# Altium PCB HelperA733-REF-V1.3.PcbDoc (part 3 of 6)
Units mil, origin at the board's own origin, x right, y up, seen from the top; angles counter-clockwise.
Board outline 5905.51 x 4133.86 mil, 2 copper layers (Top, Bottom), stack 12.7 mil thick; 446 components, 341 nets, 1706 pads, 1667 vias.
Unrouted connection lines stored in the file: 1382.
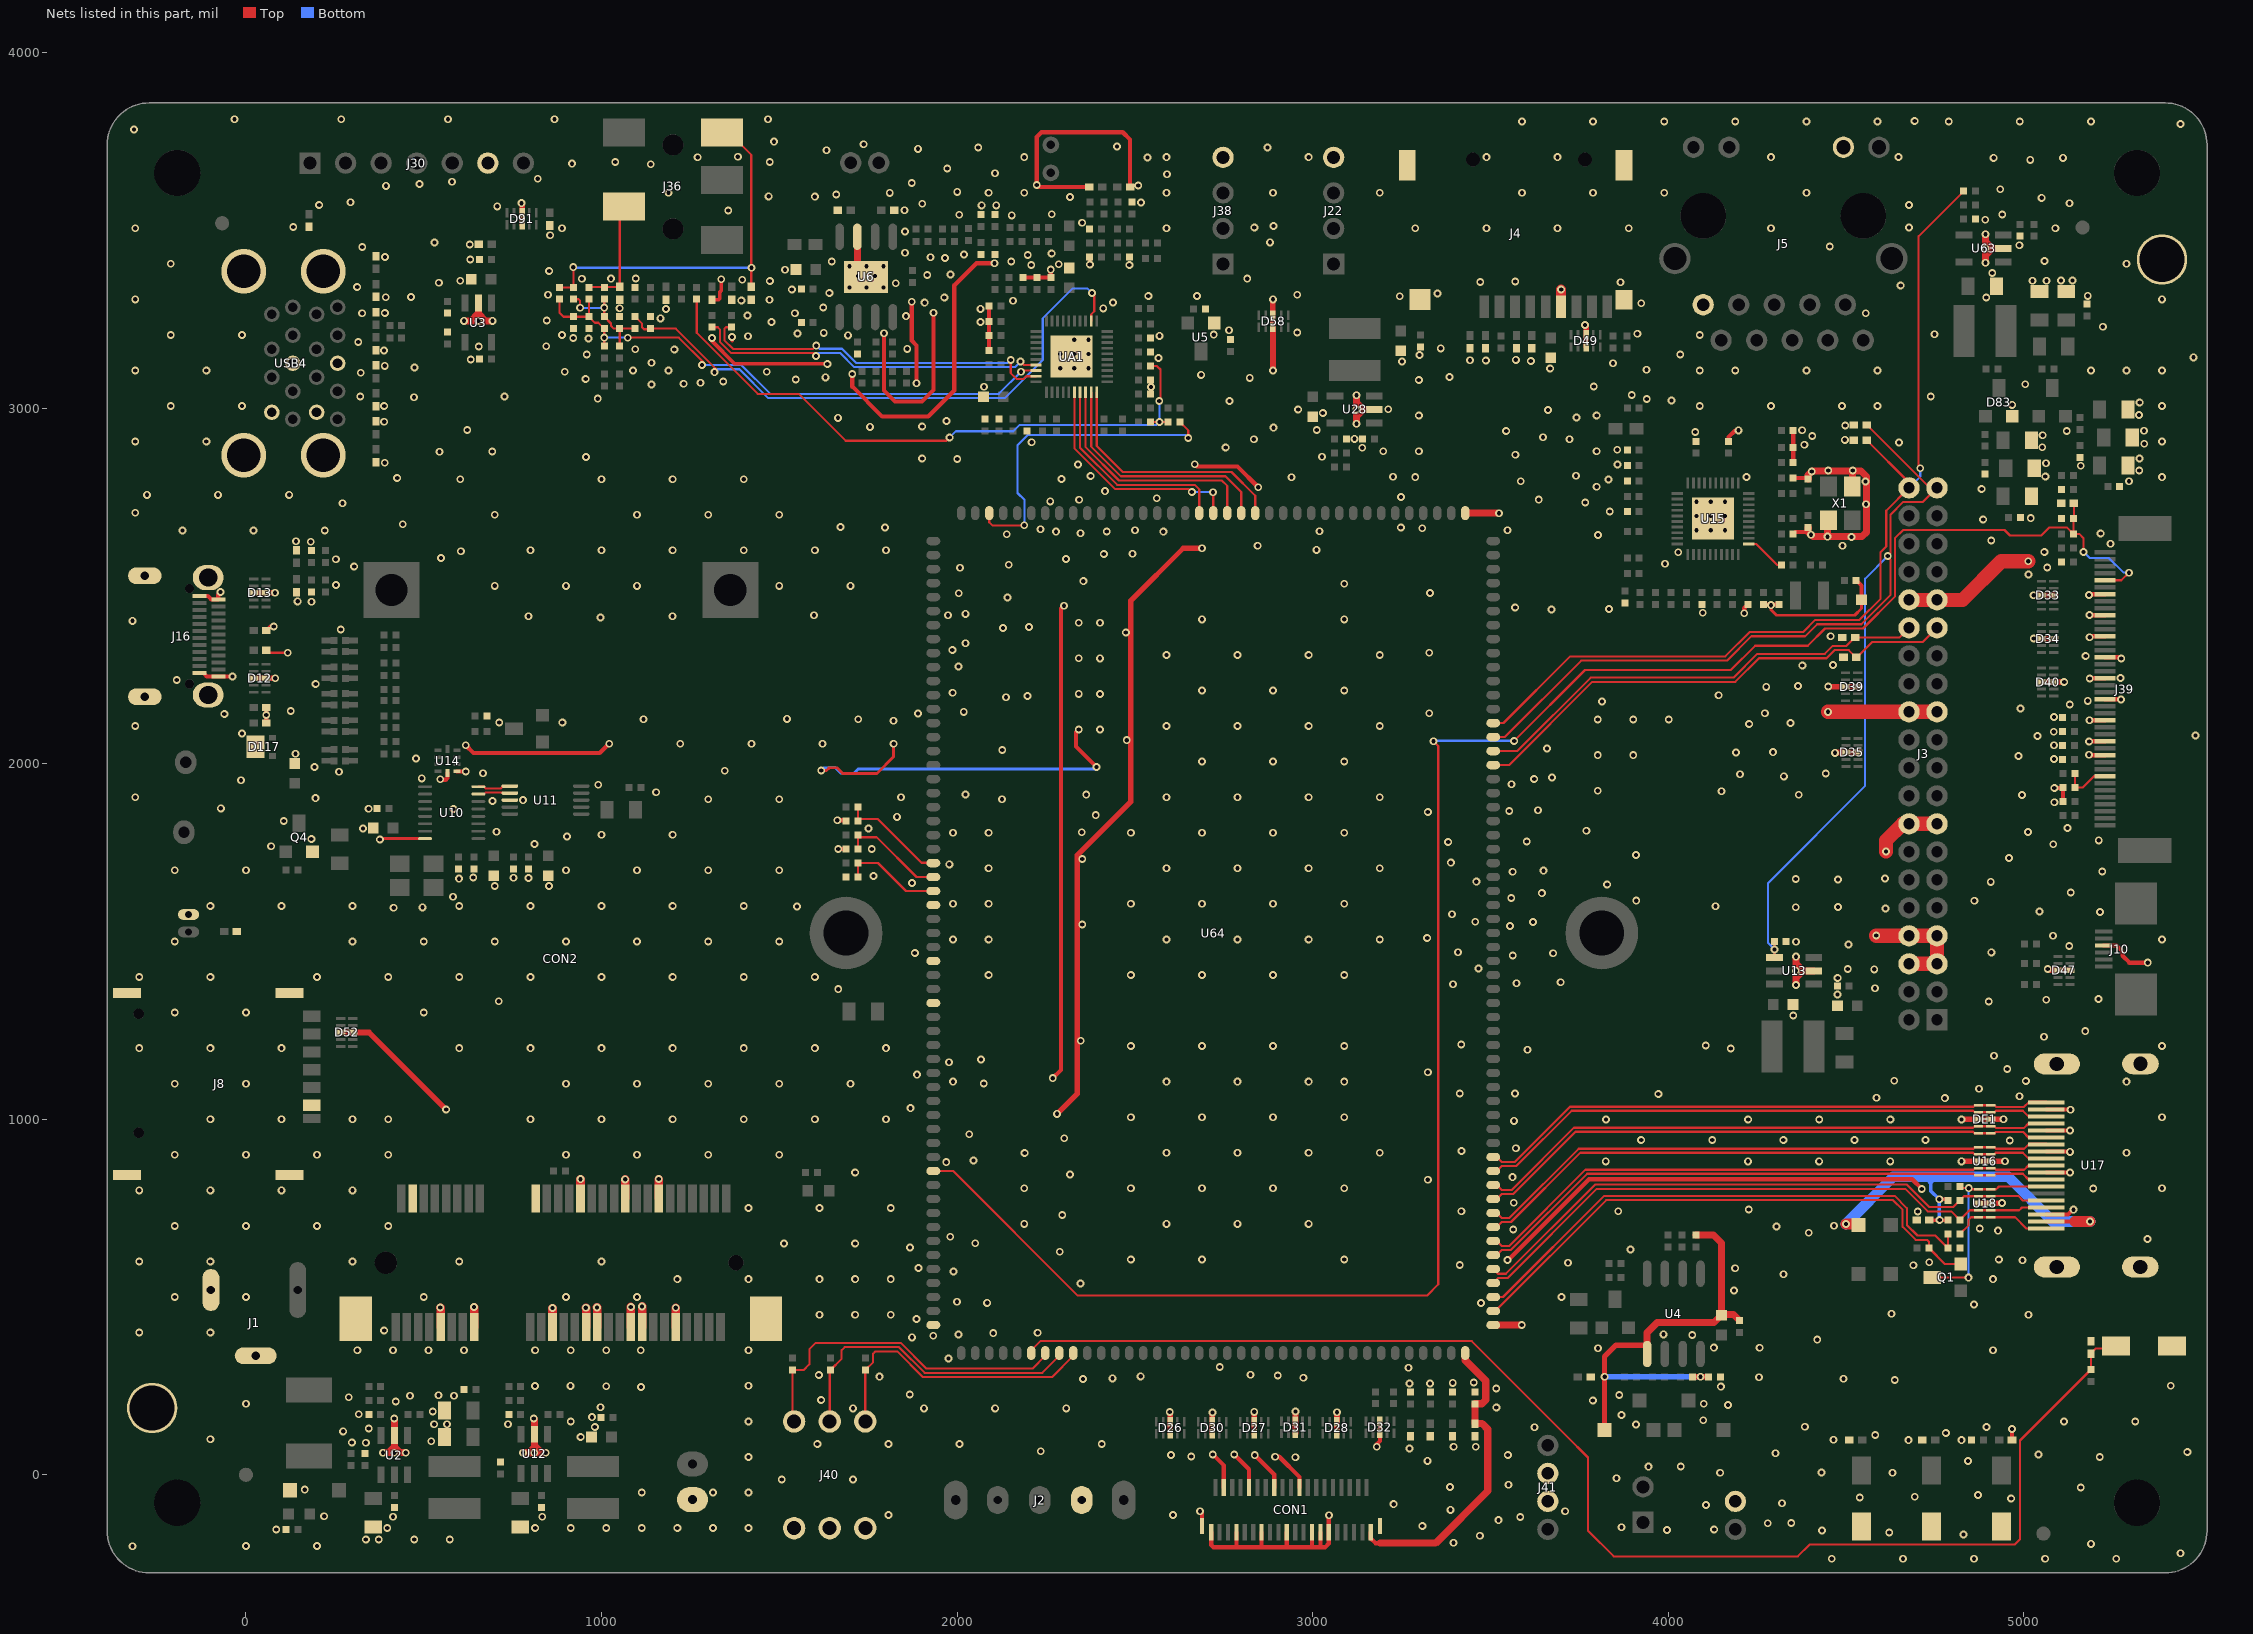
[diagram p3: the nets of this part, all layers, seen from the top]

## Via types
v1: diameter 22, hole 12, Top to Bottom, 1667 vias

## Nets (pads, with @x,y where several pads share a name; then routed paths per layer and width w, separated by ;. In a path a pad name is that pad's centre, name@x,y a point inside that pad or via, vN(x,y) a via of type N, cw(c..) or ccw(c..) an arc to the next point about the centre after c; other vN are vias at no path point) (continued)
GND: C2.2 C3.2 C4.1 C5.2 C6.2 C54.2 C55.2 C58.2 C59.2 C60.2 C69.2 C70.2 C71.2 C73.2 C75.2 C81.1 C90.2 C91.2 C94.2 C95.2 C96.2 C97.2 C173.2 C174.2 C175.2 C176.2 C177.2 C178.2 C179.2 C180.2 C183.2 C184.2 C190.2 C193.2 C197.2 C215.2 C216.2 C220.2 C223.1 C224.1 C226.1 C230.2 C231.1 C232.2 C233.2 C234.2 C235.1 CA1.1 CA2.2 CA3.1 CA4.1 CA5.1 CA10.2 CA11.2 CA12.2 CA13.2 CA14.2 CA17.2 CA18.1 CA23.2 CA25.2 CA83.1 CA89.2 CE4.1 CE5.1 CE7.1 CE8.1 CE9.1 CE11.1 CE12.1 CE13.1 CE14.1 CE15.1 CE17.1 CE18.1 CE19.1 CE20.1 CE21.1 CON1.1 CON1.4 CON1.7 CON1.10 CON1.13 CON1.16 CON1.19 CON1.22 CON1.25 CON1.27 CON1.29 CON1.40 CON1.41 CON2.4 CON2.9 CON2.15 CON2.18 CON2.21 CON2.26 CON2.27 CON2.29 CON2.34 CON2.35 CON2.37 CON2.40 CON2.43 CON2.M1 CON2.M2 CP5.2 CP6.2 CP7.2 CP8.2 CU1.1 CU2.1 CU3.1 CU7.2 D1.2 D2.1 D4.1 D5.1 D6.2 D7.2 D8.2 D9.2 D10.2 D11.2 D12.3 D12.8 D13.3 D13.8 D15.1 D16.1 D17.1 D18.1 D19.1 D20.1 D26.3 D26.8 D27.3 D27.8 D28.3 D28.8 D30.3 D30.8 D31.3 D31.8 D32.3 D32.8 D33.3 D33.8 D34.3 D34.8 D35.3 D35.8 D39.3 D39.8 D40.3 D40.8 D41.2 D42.2 D43.2 D44.2 D45.2 D47.3 D47.8 D49.3 D49.8 D52.3 D52.8 D58.3 D58.8 D67.1 D70.2 D71.2 D72.2 D73.2 D74.2 D75.2 D82.1 D83.2 D84.2 D87.2 D88.2 D90.2 D91.3 D91.8 D117.3 D118.1 D126.1 D127.1 D128.1 D129.1 D130.2 D170.2 D171.2 D172.1 D174.1 D175.1 D176.1 D177.1 D178.1 DA1.1 DA2.1 DE1.3 DE1.8 FID4.1 FID6.1 J1.2 J1.3 J2.3 J3.5 J3.6 J3.7 J3.8 J3.15 J3.16 J3.23 J3.24 J3.31 J3.32 J4.6 J4.10 J4.11 J4.12 J4.13 J5.10 J5.12 J8.5 J8.8 J8.9 J8.10 J8.11 J10.3 J14.1 J16.1 J16.2 J16.3 J16.4 J16.A1 J16.A12 J16.B1 J16.B12 J22.4 J30.6 J38.4 J39.7 J39.10 J39.13 J39.16 J39.19 J39.22 J39.25 J39.28 J39.30 J40.4 J40.5 J40.6 J41.2 J41.3 J42.2 K1.2 K2.1 K3.1 K4.2 Q4.2 R4.1 R5.2 R6.2 R25.2 R26.2 R32.2 R37.1 R38.1 R49.2 R60.1 R62.1 R150.1 R159.2 R165.1 R166.1 R174.2 R179.1 R203.2 R204.2 R205.2 R208.2 R215.2 R216.2 R217.2 R218.2 R235.2 R266.2 R279.2 R281.2 R289.2 R292.2 RA6.1 RA8.2 RA13.2 RA26.2 RA61.2 RA65.1 RE22.1 RE23.1 RE34.1 RU1.1 RU7.1 RU25.2 RU110.2 U2.2 U3.2 U5.1 U6.7 U6.9 U10.8 U11.3 U12.2 U13.2 U14.5 U14.6 U15.41 U16.3 U16.8 U17.2 U17.5 U17.8 U17.11 U17.17 U17.20 U17.21 U17.22 U17.23 U18.3 U18.8 U28.2 U63.2 U64.38 U64.95 U64.158 U64.162 U64.165 U64.188 UA1.41 USB4.4 USB4.7 USB4.13 USB4.16 USB4.19 USB4.20 USB4.21 USB4.22 X1.2 X1.4 | length 18443.2
  Top w7: D7.2@57.37,2318.9 64.78,2311.49 117.81,2311.49 v1(117.81,2311.89)
  Top w8: v1(376.65,1787.03) 378.79,1789.17 U10.8@503.94,1789.17 ; v1(1618.22,1980.71) 1618.22,1980.99 1633.23,1980.99 1640.59,1988.35 1662.26,1988.35 1678.32,1972.29 1774.41,1972.29 1821.53,2019.41 v1(1821.53,2056.01) ; v1(4288.79,2445.82) 4288.79,2432.83 4304.34,2417.28 4524.55,2417.28 4543.7,2436.43 CE7.1@4543.7,2460.63
  Top w10: v1(1310.6,3197.18) 1310.6,3188.49 1375,3124.09 v1(1635.19,3124.09) ; D17.1@1311.02,3304.83 1329.51,3304.83 1333.14,3308.46 1333.14,3326.47 1336.84,3330.17 1336.84,3362.19 v1(1336.61,3362.42) ; 1367.1,3189.01 v1(1367.1,3200.01)
  Top w11.81: J16.B1@-130.9,2254.92 -119.82,2254.92 -109.98,2245.08 J16.A12@-77.76,2245.08 -77.59,2245.25 v1(-37.99,2245.25) ; J16.B12@-130.9,2471.46 -107.17,2471.46 -97.32,2461.61 J16.A1@-77.76,2461.61 -77.76,2476.48 v1(-71.29,2482.94) ; v1(57.34,2136.92) D10.2@57.37,2157.48 ; D11.2@57.37,2114.17 v1(57.34,2136.92) ; D6.2@57.37,2374.02 69.01,2385.65 v1(78.25,2385.65) ; v1(546.26,1955.93) 547.42,1954.76 561.8,1954.76 566.93,1959.89 U14.5@566.93,1974.02 ; U14.6@593.51,1978.34 618.15,1978.34 v1(618.15,1978.17) ; v1(618.16,2051.76) 640.27,2029.65 995.17,2029.65 v1(1021.53,2056.01) ; v1(1663.31,1841.02) 1685.55,1841.02 R235.2@1687.99,1838.58 ; v1(1665.7,1759.84) R279.2@1687.99,1759.84 ; v1(1705.41,3095.77) 1705.41,3060.24 1789.33,2976.31 1919.04,2976.31 1992.03,3049.31 1992.03,3345.17 2054.25,3407.38 v1(2105.19,3407.38) ; v1(1794.74,3210.53) 1794.74,3049.27 1825.74,3018.27 1901.06,3018.27 1933.55,3050.76 v1(1933.55,3267.89) ; v1(1872.37,3298.93) 1872.37,3189.9 1885.95,3176.32 v1(1885.95,3069.84) ; CA10.2@2089.57,3161.42 CA2.2@2089.57,3204.72 RA6.1@2089.57,3244.09 CA4.1@2089.57,3287.4 ; CA14.2@2185.04,3367.13 RA8.2@2224.41,3367.13 RA26.2@2263.65,3367.13 ; v1(2263.65,3389.37) RA26.2@2263.65,3367.13 ; RA26.2@2263.78,3367.13 RA26.2@2263.65,3367.13 ; v1(2269.1,1115.59) 2292.35,1138.84 2292.35,2436.54 2299.91,2444.1 v1(2300.84,2444.1) ; v1(2342.28,2096.31) 2334.6,2088.64 2334.6,2047.96 v1(2391.98,1990.58) ; DA1.1@2371.76,3622.05 2229.44,3622.05 v1(2224.12,3627.37) 2224.12,3762.61 2237.2,3775.69 2465.95,3775.69 2486.5,3755.14 DA2.1@2486.5,3622.05 ; CA5.1@2373.03,3425.2 2373.46,3424.77 v1(2373.46,3403.8) ; v1(2668.47,2841.93) 2674.89,2835.51 2788.86,2835.51 v1(2846.9,2777.47) ; v1(2683.18,-102.26) 2689.1,-108.18 CON1.41@2689.1,-144.16 ; CON1.1@2714.69,-161.38 2714.69,-197.63 2721.06,-204 2785.56,-204 ; v1(2719.22,56.88) 2750.12,25.97 CON1.4@2750.12,-35.4 ; v1(2779.58,57.14) 2820.99,15.72 CON1.10@2820.99,-35.4 ; CON1.7@2785.56,-161.38 2785.56,-204 ; v1(2837.29,55.33) 2891.86,0.75 CON1.16@2891.86,-35.4 ; CON1.13@2856.42,-161.38 2856.42,-204 ; v1(2894.48,50.68) 2906.17,50.68 2962.72,-5.87 CON1.22@2962.72,-35.4 ; CON1.19@2927.29,-161.38 2927.29,-204 ; CON1.25@2998.15,-161.38 2998.15,-204 ; CON1.27@3021.78,-161.38 3021.78,-204 ; v1(3046.1,-113.53) 3045.4,-113.53 CON1.29@3045.4,-161.38 3045.4,-193.52 3034.92,-204 3021.78,-204 ; v1(3180.47,78.96) 3180.47,86.2 3188.98,94.71 D32.8@3188.98,116.82 D32.3@3188.98,150.9 ; v1(3548.1,603.87) 3550.04,603.87 3777.23,831.06 4686.27,831.06 4713.42,803.91 v1(4712.99,803.47) ; CE5.1@4169.29,2906.5 4169.29,2918.25 4188.39,2937.35 v1(4197.46,2937.35) ; v1(4213.58,2422.97) 4213.58,2437 RE23.1@4224.41,2447.84 ; CE14.1@4267.72,2447.84 CE12.1@4311.02,2447.84 ; R150.1@4351.38,2645.67 4357.48,2651.77 4393.46,2651.77 ; CE20.1@4351.38,2803.15 4393.64,2803.15 4393.7,2803.15 CE17.1@4393.7,2800.2 ; RE22.1@4351.38,2846.46 CE9.1@4351.38,2889.76 C81.1@4351.38,2937.01 ; CE8.1@4528.54,2515.75 4543.7,2500.59 CE7.1@4543.7,2460.63 ; D4.1@4966.82,98.43 v1(4966.82,129.01) ; U17.17@5062.99,732.28 5124.66,732.28 5138.77,746.39 v1(5139.47,745.7) ; U17.11@5062.99,850.39 5129.91,850.39 v1(5130.02,850.29) ; U17.8@5062.99,909.45 5128.68,909.45 v1(5129.93,908.2) ; U17.5@5062.99,968.5 5129.79,968.5 v1(5129.87,968.58) ; U17.2@5062.99,1027.56 5130.48,1027.56 v1(5131.21,1026.83) ; v1(5085.86,1931.56) R203.2@5110.24,1931.56 ; R204.2@5110.24,1893.7 R203.2@5110.24,1931.56 ; R203.2@5110.24,1933.07 R203.2@5110.24,1931.56 ; v1(5183.04,2025.23) 5188.31,2023.62 J39.30@5228.35,2023.62 ; v1(5183.55,2474.55) 5188.64,2476.38 J39.7@5228.35,2476.38 ; v1(5183.77,2062.18) 5188.97,2062.99 J39.28@5228.35,2062.99 ; v1(5184.42,2121.88) 5184.42,2122.05 J39.25@5228.35,2122.05 ; v1(5185.05,2418.19) 5187.41,2417.32 J39.10@5228.35,2417.32 ; v1(5185.13,2355.5) 5189.53,2358.27 J39.13@5228.35,2358.27 ; v1(5185.23,2239.29) 5190.05,2240.16 J39.19@5228.35,2240.16 ; J10.3@5224.41,1488.19 5260.85,1488.19 5277.41,1471.63 5277.41,1459.75 5296.8,1440.36 v1(5348.48,1440.36) ; J39.22@5228.35,2181.1 5270.9,2181.1 v1(5273.51,2180.27) ; J39.16@5228.35,2299.21 5269.01,2299.21 v1(5273.91,2296.03) ; 2785.56,-204 2856.42,-204 ; 2856.42,-204 2927.29,-204 ; 2927.29,-204 2998.15,-204 ; 2998.15,-204 3021.78,-204
  Top w15: D91.3@777.38,3514.99 D91.8@777.38,3549.44 ; v1(2281.16,1015.07) 2337.61,1071.52 2337.61,1742.07 2488.68,1893.14 2488.68,2458.31 2636.14,2605.77 v1(2688.7,2605.77)
  Top w16: D12.3@22.33,2240.16 D12.8@56.41,2240.16 56.48,2240.23 v1(82.49,2240.23) ; D13.3@22.33,2480.32 81.67,2480.32 v1(81.67,2480.61) ; D52.8@266.42,1244.09 D52.3@300.5,1244.09 346.46,1244.09 v1(562.99,1027.56) ; v1(774.79,3576.31) 777.38,3576.31 D91.8@777.38,3549.44 ; v1(2598.06,176.62) 2599.43,175.24 D26.8@2599.43,149.36 D26.3@2599.43,115.28 ; D30.3@2717.54,115.28 D30.8@2717.54,149.36 2717.54,174.95 v1(2718.08,175.48) ; D27.3@2835.65,115.28 2835.65,147.15 2835.74,147.23 v1(2835.74,177) ; v1(2888.7,3105.77) 2888.7,3225.87 D58.8@2887.79,3226.77 D58.3@2887.79,3261.22 2887.79,3304.87 v1(2888.7,3305.77) ; D31.3@2951.48,116.17 2951.48,148.11 2951.78,148.41 v1(2951.78,178.25) ; D28.3@3067.94,115.28 3067.94,146.55 3068.28,146.89 v1(3068.28,176.07) ; v1(3766.08,3233.43) 3769.69,3233.43 D49.8@3769.69,3206.3 D49.3@3769.69,3171.85 ; v1(4450.22,2217.01) 4450.7,2216.54 D39.8@4498.71,2216.54 D39.3@4532.79,2216.54 ; v1(4468.72,2030.41) 4469.8,2031.5 D35.8@4499.69,2031.5 D35.3@4533.77,2031.5 ; v1(4824.44,881.54) 4824.79,881.89 U16.3@4872.72,881.89 U16.8@4906.8,881.89 v1(4946.8,881.89) ; v1(4824.73,999.09) 4825.64,1000 DE1.3@4872.72,1000 DE1.8@4906.8,1000 v1(4942.72,1000) ; U18.3@4872.72,763.78 4938,763.78 v1(4938.58,764.36) ; v1(5027.59,2473.64) v1(5027.59,2473.64) D33.3@5049.89,2473.73 D33.8@5083.97,2473.73 ; v1(5028.02,2351.74) D34.3@5049.89,2351.69 D34.8@5083.97,2351.69 ; D40.3@5049.89,2229.64 D40.8@5083.97,2229.64 v1@5113.39,2229.64 ; v1(5067.2,1422.4) 5071.03,1418.57 D47.3@5095.93,1418.57 D47.8@5130.01,1418.57
  Top w20: v1(385.32,62.24) 405.32,62.24 ; v1(417.32,158.24) U2.2@417.32,110.24 417.32,78.24 ; v1(449.32,62.24) 433.32,62.24 ; v1(613.54,3245.28) 633.54,3245.28 ; U3.2@653.54,3295.28 653.54,3265.28 ; v1(693.54,3245.28) 673.54,3245.28 ; v1(779.02,62.17) 795.02,62.17 ; v1@811.02,156.54 U12.2@811.02,114.17 811.02,78.17 ; v1(843.02,62.17) 831.02,62.17 ; U6.7@1719.4,3481.79 1719.4,3397.73 1721.2,3395.93 v1(1721.2,3371.17) ; v1(3123.23,2956.06) 3123.23,2976.06 ; v1(3123.23,3036.06) 3123.23,3016.06 ; U28.2@3173.23,2996.06 3143.23,2996.06 ; U64.95@3429.13,2704.73 3516.58,2704.72 v1(3524,2704) ; U64.38@3507.87,421.26 v1(3587.87,421.26) ; v1(4359.45,1377.32) 4359.45,1397.32 ; v1(4359.45,1457.32) 4359.45,1437.32 ; CE18.1@4393.7,2664.37 4393.46,2651.77 4406.65,2638.58 v1@4447.88,2638.58 ; CE17.1@4393.7,2800.2 4393.64,2803.15 4393.46,2811.96 4403.27,2821.77 4404.59,2823.09 v1@4517.72,2823.09 ; U13.2@4409.45,1417.32 4379.45,1417.32 ; v1(4447.88,2638.43) v1@4447.88,2638.58 ; X1.2@4450.79,2685.04 4447.88,2682.13 v1@4447.88,2638.58 ; X1.4@4517.72,2779.53 v1@4517.72,2823.09 ; v1(4891.93,3408.82) 4891.93,3428.82 ; v1(4891.93,3488.82) 4891.93,3468.82 ; U63.2@4941.93,3448.82 4911.93,3448.82 ; 405.32,62.24 405.32,66.24 417.32,78.24 ; 405.32,62.24 v1(417.32,62.24) ; v1(417.32,62.24) 433.32,62.24 ; v1(417.32,62.24) 417.32,78.24 ; 417.32,78.24 433.32,62.24 ; 633.54,3245.28 653.54,3265.28 ; 633.54,3245.28 v1(653.54,3245.28) ; v1(653.54,3245.28) 673.54,3245.28 ; v1(653.54,3245.28) 653.54,3265.28 ; 653.54,3265.28 673.54,3245.28 ; 795.02,62.17 v1(811.02,62.17) ; 795.02,62.17 807.02,74.17 811.02,74.17 ; v1(811.02,62.17) 831.02,62.17 ; v1(811.02,62.17) 811.02,74.17 ; 811.02,74.17 811.02,78.17 ; 811.02,78.17 815.02,78.17 831.02,62.17 ; 3123.23,2976.06 3143.23,2996.06 ; 3123.23,2976.06 v1(3123.23,2996.06) ; v1(3123.23,2996.06) 3123.23,3016.06 ; v1(3123.23,2996.06) 3143.23,2996.06 ; 3123.23,3016.06 3143.23,2996.06 ; 4359.45,1397.32 v1(4359.45,1417.32) ; 4359.45,1397.32 4379.45,1417.32 ; v1(4359.45,1417.32) 4359.45,1437.32 ; v1(4359.45,1417.32) 4379.45,1417.32 ; 4359.45,1437.32 4379.45,1417.32 ; v1@4447.88,2638.58 4545.07,2638.58 4557.34,2650.85 4557.34,2807.71 4541.96,2823.09 v1@4517.72,2823.09 ; 4891.93,3428.82 v1(4891.93,3448.82) ; 4891.93,3428.82 4911.93,3448.82 ; v1(4891.93,3448.82) 4891.93,3468.82 ; v1(4891.93,3448.82) 4911.93,3448.82 ; 4891.93,3468.82 4911.93,3448.82
  Top w24: v1(546.55,470.23) 547.25,470.23 CON2.9@547.25,415.42 ; v1(641.52,471.69) 641.74,471.47 CON2.15@641.74,415.42 ; v1(861.87,468.86) 862.21,468.86 CON2.21@862.21,415.42 ; v1(940.83,831.58) 940.95,831.58 CON2.26@940.95,777.62 ; v1(955.93,470.08) 956.7,470.08 CON2.27@956.7,415.42 ; v1(987.04,470.62) 988.19,470.62 CON2.29@988.19,415.42 ; v1(1066.45,830.87) 1066.93,830.87 CON2.34@1066.93,777.62 ; v1(1082.53,472.26) 1082.68,472.26 CON2.35@1082.68,415.42 ; CON2.37@1114.18,415.42 v1(1114.18,473.35) ; v1(1160.79,831.81) 1161.42,831.81 CON2.40@1161.42,777.62 ; v1(1208.58,470.08) 1208.66,470.08 CON2.43@1208.66,415.42
  Top w28: J4.6@3698.82,3285.43 v1(3698.82,3333.43)
  Top w40: v1(4449.38,2145.67) J3.24@4677.17,2145.67 4711.46,2145.67 J3.23@4755.91,2145.67 ; v1(4585.01,1516.71) 4585.01,1516.23 4677.17,1516.23 J3.8@4677.17,1515.75 J3.7@4755.91,1515.75 J3.5@4755.91,1437.01 J3.6@4677.17,1437.01 ; v1(4612.74,1752.97) 4612.74,1783.97 4659.48,1830.71 J3.16@4677.17,1830.71 J3.15@4755.91,1830.71 ; J3.32@4677.17,2460.63 4715.74,2460.63 J3.31@4755.91,2460.63 4827.91,2460.63 4936.33,2569.05 v1(5012.26,2569.05)
  Bottom w8: v1(1618.22,1980.71) 1618.22,1980.98 1625.59,1988.35 1658.1,1988.35 1673.58,1972.87 1710.16,1972.87 1722,1984.72 2386.11,1984.72 v1(2391.98,1990.58)
  other v1: 4460,-236 4660,-236 4860,-236 5060,-236 5260,-236 5440.94,-220.47 -318.9,-200.79 0,-200 200,-200 5188.7,-194.23 3396.22,-190.89 337.32,-181.76 373.32,-181.76 473.32,-181.76 573.32,-181.76 3470.18,-171.46 4830.08,-168.15 4621.41,-162.03 4432.51,-156.37 3996.67,-155.12 85.32,-153.76 4129.03,-153.88 397.32,-149.76 813.32,-149.76 913.32,-149.76 1013.32,-149.76 1113.32,-149.76 1213.32,-149.76 1313.32,-149.76 1413.32,-149.76 3868.86,-147.68 3308.45,-144.26 4280,-136 4345.96,-135.2 3522.94,-127.53 3584.04,-118.48 413.32,-117.76 833.32,-117.76 219.95,-116.69 1807.04,-113.16 2607.04,-113.16 3710.01,-102.64 3387.42,-98.57 4106.46,-84.83 3227.72,-82.46 4320,-80 4964.33,-66.41 4538.5,-64.05 4693.48,-61.7 4871.13,-56.71 1113.32,-49.76 1313.32,-49.76 1413.32,-49.76 165.32,-41.76 5160,-36 3386.42,-34 3550.85,-27.97 1507.04,-13.16 1707.04,-13.16 3854.59,-9.59 4630.83,5.66 4145.99,5.71 4430.91,6.49 3944.5,22.93 4035.04,23.57 4842.8,38.64 3322.75,39.18 2951.38,49.37 1413.32,50.24 5213.32,50.24 2658.39,51.42 2601.39,55.75 3548.97,55.93 5041.5,56.95 4301.6,60.83 5460,64 2235.14,66.03 3272.62,74.2 3396.53,78.92 3458.68,78.92 1607.04,86.84 1807.04,86.84 2007.04,86.84 2407.04,86.84 337.32,90.24 297.95,91.16 521.32,94.24 4675.9,97.53 4825.05,97.53 4464.73,98.52 -100,100 941.32,106.24 4582.09,111.84 4780.74,117.62 273.32,122.24 345.32,130.24 981.32,134.24 3623.84,133.85 4894.87,134.23 4384.28,134.96 529.32,142.24 565.32,142.24 737.32,142.24 3909.45,141.73 913.32,150.24 1413.32,150.24 5113.32,150.24 5313.32,150.24 4098.43,153.54 809.32,158.24 973.32,162.24 3868.7,168.21 317.32,170.24 525.32,178.24 1707.04,186.84 1907.04,186.84 2107.04,186.84 2307.04,186.84 3516.64,189.26 997.32,190.24 4167.82,196.55 0,200 4100,200 421.32,206.24 3787.99,209.13 1617.72,210.1 289.32,218.24 461.32,222.24 585.32,222.24 541.44,223.73 3862.26,224.67 1867.04,225.56 3516.3,242.89 1110.85,247 4148,248 1013.2,249.22 812.99,249.72 913.01,250.11 1413.32,250.24 5413.32,250.24 3272.08,256.66 3330.18,257.03 3393.93,258.57 3452.93,259.62 4636.89,266.72 2353.79,269.71 4493.18,270.37 2436.79,271.28 2973.83,272.99 4255.21,274.39 1781.58,276.14 2516.25,276.88 2901.74,279.47 1611.27,280.77 2824.9,281.2 3269.48,301.01 2738.51,303.33 1975.63,327 313.32,350.24 413.32,350.24 513.32,350.24 613.32,350.24 813.32,350.24 913.32,350.24 1013.32,350.24 1110.34,350.19 1413.32,350.24 4913.32,350.24 3802.79,355.99 4257,357.38 4128.28,357.71 4419.03,380.16 1873.3,386.5 1933.07,391.26 4067.5,393.02 2003.93,394.8 3986.9,395.05 2101.47,398.48 2226.49,399.39 -300,400 -100,400 388.7,405.77 1885.76,438.37 1613.32,450.24 1713.32,450.24 1813.32,450.24 5013.32,450.24 4628.14,453.02 4859.83,479.3 2084.58,483.59 3473.44,483.33 1999.51,486.53 -200,500 0,500 500,500 900,500 1100,500 3700,500 4185.19,518.22 2346.89,537.77 1213.32,550.24 1413.32,550.24 1613.32,550.24 1713.32,550.24 1813.32,550.24 4913.32,550.24 4324.4,564.03 1990.01,571.52 1891.51,581.51 4188.16,580.69 4689.37,589.35 3413.43,590.38 3718.13,596.42 4734.03,597.93 -300,600 -100,600 300,600 600,600 1000,600 4996.23,603.29 4929.81,605.33 2488.7,605.77 2688.7,605.77 3088.7,605.77 2288.77,627.13 3893.99,633.75 1867.77,639.07 1513.32,650.24 1713.32,650.24 2051.21,651.23 5347.72,662.96 1980.89,669.29 4395.31,680.61 4927.1,686.66 3564.11,689.78 4876.27,692.76 4304.67,698.52 -200,700 0,700 200,700 400,700 4466.08,700.64 2188.7,705.77 2588.7,705.77 2788.7,705.77 2988.7,705.77 2295.93,730.99 4701.96,740.26 3418.19,741.26 3859.32,740.99 4226.54,746.44 1413.32,750.24 1613.32,750.24 1813.32,750.24 3565.5,765.11 -300,800 -100,800 100,800 300,800 5195.23,805.29 2188.7,805.77 2488.7,805.77 2688.7,805.77 2888.7,805.77 3088.7,805.77 5388.7,805.77 3324,830 3562.04,837.2 2317.35,844.87 1713.32,850.24 1969.65,879.33 3824.44,881.54 4224.44,881.54 4424.44,881.54 4624.44,881.54 2045.91,883.75 -200,900 0,900 200,900 400,900 900,900 1100,900 1300,900 1500,900 2190.03,905.18 2588.7,905.77 2788.7,905.77 2988.7,905.77 3188.7,905.77 5288.7,905.77 3418.62,910.78 3571.43,918.2 4960.23,940.43 3923.77,941.37 4123.77,941.37 4323.77,941.37 4523.77,941.37 4723.77,941.37 2301.27,946.72 2034.15,957.84 3566.19,995.37 3824.73,999.09 4224.73,999.09 4424.73,999.09 4624.73,999.09 -100,1000 100,1000 300,1000 400,1000 800,1000 1000,1000 1200,1000 1400,1000 1600,1000 1800,1000 2488.7,1005.77 2688.7,1005.77 2888.7,1005.77 3088.7,1005.77 5388.7,1005.77 1868.96,1031.15 4778.02,1059.38 4585.42,1060.44 4987.64,1064.7 3972.22,1071.26 3413.55,1072.16 3569.26,1072.06 4873.79,1085.98 -200,1100 0,1100 900,1100 1100,1100 1300,1100 1500,1100 1700,1100 2075.16,1100.43 1988.7,1105.77 2588.7,1105.77 2788.7,1105.77 2988.7,1105.77 3088.7,1105.77 5288.7,1105.77 5005.73,1107.26 4635.44,1108.33 1887.41,1125.45 3324,1132 4953.58,1141.14 1977.12,1160.09 2067.01,1167.73 4916.35,1178.56 3604.08,1195.17 4175.85,1198.92 -300,1200 -100,1200 100,1200 600,1200 800,1200 1000,1200 1200,1200 1400,1200 1600,1200 1800,1200 2488.7,1205.77 2688.7,1205.77 2888.7,1205.77 3088.7,1205.77 5388.7,1205.77 4105.36,1207.05 3418,1210 2347.77,1220.52 5056.81,1231.76 5172.79,1247.72 4351.71,1291.66 -200,1300 0,1300 500,1300 4901.29,1330.95 711.02,1332.03 5063.19,1336.04 5210.03,1338.17 4476.12,1350.57 1665.71,1365.9 4581.64,1368.29 3394.71,1379.71 3573.36,1382.35 3697.39,1385.06 4476.44,1397.08 -300,1400 -100,1400 200,1400 400,1400 600,1400 800,1400 1000,1400 1200,1400 1400,1400 1600,1400 2088.7,1405.77 2488.7,1405.77 2688.7,1405.77 2888.7,1405.77 3088.7,1405.77 4579.51,1421.5 4505.03,1422.56 3466.46,1423.97 3562.77,1460.79 1881.23,1467.59 3676.3,1466.84 4908.74,1469.28 3408.45,1469.77 5127.93,1487.37 4506.67,1491.29 4359.04,1498.95 -200,1500 300,1500 500,1500 700,1500 900,1500 1100,1500 1300,1500 1500,1500 1988.7,1505.77 2088.7,1505.77 2588.7,1505.77 2788.7,1505.77 2988.7,1505.77 3188.7,1505.77 5388.7,1505.77 3322,1510 5082.18,1516.1 3555.28,1543.43 2352.24,1547.56 3619.6,1554.65 3457.3,1555.25 3391.66,1576.62 5214.12,1583.14 5043.87,1584.2 4611.17,1592.9 415.4,1594.54 496.73,1595.89 4358.37,1596.29 4477.65,1596.97 1549.99,1598.6 4132.8,1599.15 -100,1600 100,1600 300,1600 600,1600 800,1600 1000,1600 1200,1600 1400,1600 1988.7,1605.77 2088.7,1605.77 2488.7,1605.77 2688.7,1605.77 2888.7,1605.77 3088.7,1605.77 4860.86,1614.6 3910.12,1614.81 3558.3,1621.99 582.13,1625.71 3644.64,1635.81 5132.19,1637.4 699.68,1655.69 852.56,1655.8 3828.11,1660.22 1873.5,1664.14 4907.07,1667.54 3460.35,1668.21 4477.65,1674.23 4358.37,1675.58 599.5,1676.64 4609.81,1676.94 794.9,1678.54 639.5,1679.68 752.24,1678.92 1765.1,1683.85 3562.39,1695.87 5220.51,1696.99 3649.28,1699.17 -200,1700 0,1700 900,1700 1100,1700 1300,1700 1500,1700 2088.7,1705.77 2588.7,1705.77 2788.7,1705.77 2988.7,1705.77 3188.7,1705.77 1978.29,1716.75 3388.61,1721.64 2352.24,1731.7 4958.45,1734.45 3909.44,1742.91 1759.84,1759.84 70.87,1767.72 5082.89,1773.25 811.44,1774.18 3380.97,1779.64 3602.31,1781.17 5210.93,1784.24 184,1788 902.67,1795.15 1000,1800 1200,1800 1988.7,1805.77 2088.7,1805.77 2488.7,1805.77 2688.7,1805.77 2888.7,1805.77 3088.7,1805.77 2350.39,1807.09 704.5,1808.29 5011.9,1807.95 3769.74,1811.35 329.07,1817.95 1750.58,1817.97 5122.89,1819.25 106.3,1838.58 1830.71,1850.39 2390.11,1855.25 3324,1864 3552.67,1866.68 3633.54,1868.81 583.92,1872.37 345.06,1873.18 -70.47,1874.3 5085.86,1891.56 693.41,1895.17 779.19,1897.37 1300,1900 1500,1900 2126.64,1899.86 195.39,1903.04 1842.52,1905.51 -311.3,1905.77 2588.7,1905.77 2788.7,1905.77 2988.7,1905.77 3188.7,1905.77 4995.2,1911.53 2023.62,1913.39 2363.25,1912.91 4367.18,1912.8 1153.7,1919.36 4150.02,1922.39 3801.65,1923.95 990.86,1940.89 3559.06,1942.23 -14.09,1953.34 3622.9,1957.13 494.38,1958.6 3672.91,1961.38 4325.16,1964.3 4201.81,1970.4 4443.09,1972.44 666.74,1973.01 261.77,1977.38 1346.62,1980.3 193.05,1990.71 2688.7,2005.77 2888.7,2005.77 3088.7,2005.77 5085,2013.14 478.09,2014.2 4985.34,2021.6 3801.65,2023.95 3901.65,2023.95 139.37,2027.62 4190.38,2031.16 4294.41,2032.45 2126.84,2038.25 3659.18,2042.92 5084.66,2051.8 1221.53,2056.01 1421.53,2056.01 1621.53,2056.01 2477.03,2066.13 5038.2,2077.85 5482.53,2078.96 -11.06,2085.02 5084.31,2089.78 2402.17,2096.08 -311.3,2105.77 2588.7,2105.77 2788.7,2105.77 2988.7,2105.77 3188.7,2105.77 4227.57,2111.78 4344.14,2114.49 712.25,2115.74 889.95,2115.74 1820.91,2120.87 3801.65,2123.95 3901.65,2123.95 4001.65,2123.95 1118.13,2125.13 1722.1,2125.13 1521.91,2125.98 5084.66,2131.2 -60.66,2139.88 1889.89,2140.81 4271.68,2141.54 3328,2142 2018.53,2145.72 125.86,2147.78 4990.76,2155.11 5129.02,2166.63 3813.51,2175.01 5179.85,2176.61 2137.64,2186.52 2197.84,2190.12 4141.72,2192.53 2342.28,2196.31 2402.17,2196.08 1987.54,2199.35 2688.7,2205.77 2888.7,2205.77 3088.7,2205.77 4275.84,2216.03 4365.15,2218.18 196.01,2223.78 5113.39,2229.64 -194.49,2235.59 5272.13,2240.74 2004.3,2273.2 4377.19,2275.83 4463.18,2277.14 2342.28,2296.31 2402.17,2296.08 5173.92,2302.59 2588.7,2305.77 2788.7,2305.77 2988.7,2305.77 3188.7,2305.77 3328,2312 1986.68,2319.96 2023.62,2338.58 4456.69,2358.27 2474.71,2368.71 266.55,2377.1 2128.82,2381.62 2202.09,2384.54 2342.28,2396.31 2402.17,2396.08 -318.73,2401.54 2688.7,2405.77 3088.7,2405.77 997.48,2411.25 794.96,2414.59 1199.54,2414.45 1597.46,2417.26 1974.57,2417.15 2023.62,2421.26 4096.85,2424.36 3671.74,2433.41 3833.1,2434.62 3569.43,2439.03 184.36,2455.42 145.46,2456.45 2141.81,2467.04 2004.91,2479.02 3330,2480 700,2500 900,2500 1100,2500 1500,2500 1700,2500 253.21,2502.7 3088.7,2505.77 2355.16,2513.3 5013.21,2531.92 2007.87,2551.18 5065.88,2551.98 304.3,2554.44 2145.12,2559.22 3991,2562.14 252.94,2575.04 2306.35,2575.24 548.51,2578.65 2412.76,2589.47 2493.05,2590.25 4028,2594.54 5057.75,2595.36 604.5,2597.26 800,2600 1000,2600 1200,2600 1400,2600 1600,2600 1800,2600 3011.12,2601.29 2845.25,2612.64 4489.97,2612.86 5243.84,2618.51 182.27,2623.98 140.94,2625.53 4908.65,2627.89 4515.07,2637.7 3802.76,2643.16 4401.34,2643.6 2139.67,2645.21 5216.05,2646.98 2346.8,2647.88 2277.89,2652.5 2580.06,2652.48 2420.89,2653.18 3019.38,2653.44 -178.47,2656.01 21.53,2656.01 221.53,2656.01 2500.19,2656.36 3548,2656.51 4079.56,2656.43 4119.56,2656.43 4159.56,2656.43 2234.52,2659.24 3308,2662 1797.09,2664.34 3248,2664 1671.85,2665.57 440.94,2673.23 4885.6,2686.85 5019.66,2690.48 4079.56,2696.43 4119.56,2696.43 4159.56,2696.43 700,2700 1100,2700 1300,2700 1500,2700 -311.3,2705.77 3835.3,2709.04 4556.21,2729.64 271.65,2732.28 3766.82,2734.32 4079.56,2736.43 4119.56,2736.43 4159.56,2736.43 2262.25,2737.68 2343.27,2742.27 3636.01,2742.57 2561.52,2746.48 3248.66,2749.84 -278.47,2756.01 -78.47,2756.01 121.53,2756.01 2415.69,2766.47 4881.43,2772.5 3798.69,2778.82 4554.89,2793.65 3585.33,2794.42 5295.97,2794.01 3832.17,2799.32 602.8,2799.77 1000,2800 1200,2800 1400,2800 2293.58,2800.34 425.2,2803.15 2940.74,2805.34 3226.17,2806.66 3288.7,2805.77 4220.27,2806.38 5388.7,2805.77 5060.66,2807.44 2375.55,2808.78 3740.9,2809.75 4403.53,2821.5 4449.88,2824.65 4519.06,2824.43 5324.49,2824.62 5159.89,2837.94 2339.89,2841.39 3857.03,2841.42 5062.21,2844.91 390.26,2846.39 2000.38,2856.81 1901.73,2858.24 5325.49,2858.23 956.69,2862.2 3026.06,2863.02 3570.01,2868.67 544.4,2877.4 692.91,2877.95 3198.69,2878.82 3298.69,2878.82 3798.69,2878.82 3856.43,2883.03 3139.39,2888.19 2755.3,2888.93 5051.78,2889.71 4382.79,2896.73 5338.9,2899.44 4648.89,2903.25 2209.68,2904.02 -311.3,2905.77 -111.3,2905.77 5388.7,2905.77 4496.68,2910.6 2834.59,2912.41 3722.04,2912.28 3117.72,2913.41 3647.79,2918.17 4405,2921.72 5052.94,2923.69 4075.82,2932.63 5120.89,2935.25 3544.17,2935.85 5337.7,2936.05 4376.58,2937.45 622.56,2938.45 3011.42,2938.18 2889.74,2944.94 1754.99,2947.2 1901.73,2947.96 4497.72,2951.19 388.69,2961.62 1970.17,2963.93 1665.35,2972.44 3742.07,2973.56 3298.69,2978.82 3798.69,2978.82 5324.11,2980.28 3028.63,2986.3 3661.85,2994.44 2959.13,2996.3 3212.52,2996.58 388.69,3005.67 -211.3,3005.77 -11.3,3005.77 4088.7,3005.77 4288.7,3005.77 4488.7,3005.77 4588.7,3005.77 5388.7,3005.77 4967.2,3009.05 5325.69,3015.83 2766.14,3019.76 4009.13,3021.36 989.37,3026.51 3939.36,3025.86 472.86,3030.46 321.38,3032.31 726.99,3032.46 4738.38,3032.35 3897.41,3036.57 2545.07,3059 2075.58,3060.13 3790.39,3060.77 1140.4,3066.62 5003.99,3067 1230.96,3068.55 1278.64,3071.38 1342.47,3074.52 3298.69,3078.82 1546.46,3080.58 955.43,3081.59 2822.87,3084.93 1629.76,3086.39 3384.98,3087.53 2686.39,3093.38 322.75,3099.13 896.83,3102.41 1464.61,3102.38 -311.3,3105.77 -111.3,3105.77 1088.7,3105.77 1188.7,3105.77 4088.7,3105.77 4188.7,3105.77 4388.7,3105.77 4588.7,3105.77 5188.7,3105.77 5288.7,3105.77 5388.7,3105.77 3939.08,3107.82 3667.91,3111.08 2289.86,3112.26 2329.86,3112.26 2369.86,3112.26 474.36,3114.2 390.42,3118.79 3844.49,3126.09 1140.4,3127.64 3251.06,3130.85 3613.63,3132.32 3487.14,3133.52 3442.52,3134.58 3571.51,3135.59 632.39,3136.55 2566.25,3141.14 5477.14,3142.61 3300.21,3149.49 4033.58,3150.65 958.34,3150.84 2289.86,3152.26 2329.86,3152.26 2369.86,3152.26 388.17,3161.72 1095.09,3165.34 1204.88,3164.74 1859.76,3166.59 3360,3168 654.57,3173.14 844.53,3174.09 316.1,3185.67 2329.86,3192.26 2369.86,3192.26 963.64,3195.65 920.75,3197.28 1412.02,3201.87 2569.36,3203.06 1692.97,3204.52 -211.3,3205.77 -11.3,3205.77 888.7,3205.77 2721.76,3206.55 4088.7,3205.77 4748.53,3207.44 1551.01,3209.62 3913.11,3208.94 1625.11,3211.56 2956.69,3212.6 2764.78,3218.75 5222.33,3228.51 1478.36,3242.07 2066.07,3242.26 845.85,3246.53 1166.17,3252.38 1856.37,3258.61 1410.56,3260.47 326.75,3266.89 390.75,3267.4 1543.75,3266.77 4555.4,3266.7 1181.26,3278.36 2065.63,3279.02 2410.96,3280.45 1050.99,3280.98 1623.65,3282.75 3923.96,3295.01 1908.73,3296.56 2438.45,3297.24 2157.57,3301.66 1393.32,3302.88 1472.55,3304.54 -311.3,3305.77 5388.7,3305.77 393.29,3311.57 1964.24,3311 4894.23,3311.07 463.91,3312.7 3244.86,3314.67 2537.95,3315 2674.68,3314.91 5179.57,3315.61 849.65,3318.76 2956.69,3318.9 3351.27,3322.12 1640.8,3323.93 1535.31,3333.22 1697.2,3339.17 1745.2,3339.17 1793.2,3339.17 312.77,3340.78 4653.54,3344.47 1827.51,3351.15 542.52,3352.69 3471.23,3354.65 3865.67,3353.98 3569.5,3356.01 1473.52,3357.33 602.83,3358.18 5024.62,3357.98 5063.72,3358.18 5104.45,3359 5136.79,3358.8 1395.94,3360.75 944.74,3363.64 1026.7,3364.07 1096.53,3364.28 2816,3364 1769.2,3371.17 1916.33,3374.11 1981.72,3375.63 4911.08,3379.7 852.69,3385.67 1516.18,3389.05 1697.2,3399.17 1745.2,3399.17 1793.2,3399.17 2208.79,3402.63 2484.54,3402.41 2286.02,3404.37 -211.3,3405.77 5288.7,3405.77 1647.58,3412.56 2152.13,3412.31 5058.16,3413.94 631.09,3417.93 1965.76,3422.01 1925.46,3424.3 391.42,3425.01 2198.62,3430.72 2019.74,3431.9 2265.94,3434.59 1853.33,3436.84 327.03,3452.76 4454.08,3454.39 4987.48,3458 629.48,3459.92 529.99,3465.44 2880,3466 855.57,3486.2 1853.33,3496.37 -311.3,3505.77 888.7,3505.77 2588.7,3505.77 3288.7,3505.77 3488.7,3505.77 3688.7,3505.77 3888.7,3505.77 4288.7,3505.77 5088.7,3505.77 2836,3508 4677.17,3507.87 133.23,3509.56 2889.76,3511.81 2351.67,3521.14 4891.57,3529.43 2153.84,3542.03 2006.13,3543.48 2266.2,3544.93 4939.51,3544.7 1356.35,3555.69 1852.17,3556.43 706.89,3567.25 2069.09,3570.11 2110.25,3570.11 205.83,3570.98 4677.17,3570.87 1901.89,3574.84 5128.79,3576.21 2517.49,3577.92 294.36,3578.82 5050.08,3591.2 1600.03,3594.61 2317.53,3593.85 1470.01,3595.37 1660.1,3600.7 1810.65,3605.26 1188.7,3605.77 2088.7,3605.77 2188.7,3605.77 2588.7,3605.77 2888.7,3605.77 3188.7,3605.77 3588.7,3605.77 3788.7,3605.77 3988.7,3605.77 4388.7,3605.77 2000.43,3608.13 4933.88,3615.57 393.99,3624.91 2509.49,3625.92 488.2,3630.33 1872.7,3633.22 579.69,3636.43 820.71,3644.89 2590.55,3657.48 2106.88,3660.6 1972.3,3673.52 1138.65,3685.78 917.31,3687.48 1038.82,3691.78 1473.34,3691.78 5018.21,3698.03 4915.13,3703.65 5110.05,3703.65 1270.36,3705.44 2535.43,3704.72 2188.7,3705.77 2588.7,3705.77 2988.7,3705.77 3488.7,3705.77 3688.7,3705.77 4288.7,3705.77 4647.9,3706.33 1383.53,3706.78 1632.59,3724.92 1890.18,3729.03 2059.74,3732.83 2872.77,3732.84 2449.89,3735.9 1737.16,3741.92 1484.83,3749.3 -314.96,3783.46 5440.94,3799.21 3588.7,3805.77 3788.7,3805.77 3988.7,3805.77 4188.7,3805.77 4388.7,3805.77 4588.7,3805.77 4788.7,3805.77 4988.7,3805.77 5188.7,3805.77 4692.91,3807.09 -32.02,3812.17 267.98,3812.17 567.98,3812.17 867.98,3812.17 1467.98,3812.17
GND_485: C35.2 C36.2 D115.1 R45.2 R48.1 R49.1 U4.5 | length 1289.4
  Top w10: C36.2@4200.79,434.05 4201.68,434.05 C36.2@4201.68,434.94
  Top w15: D115.1@3820.76,125.98 3820.76,332.15 3853.37,364.76 3940.75,364.76 U4.5@3940.75,339.76 ; R48.1@4067.91,275.59 4067.91,275.99 v1(4090.71,275.99) 4113.19,275.99 R49.1@4113.19,275.59
  Top w20: U4.5@3940.75,364.76 3940.75,400.13 3969.02,428.39 4128.79,428.39 C35.2@4149.61,449.21 ; R45.2@4078.74,674.21 4127.26,674.21 4149.75,651.72 C35.2@4149.75,450.97 ; C36.2@4200.79,434.05 4183.87,450.97 C35.2@4149.75,450.97 ; C35.2@4149.61,449.21 4149.61,450.97 C35.2@4149.75,450.97 ; C35.2@4149.61,449.21 4149.75,449.36 C35.2@4149.75,450.97
  Bottom w15: v1(3821.18,276.02) 3955.93,276.02 ; 3955.96,275.99 v1(4090.71,275.99)
GPADC4: R234.2 R235.1 U64.155 | length 302.8
  Top w6: R235.1@1721.46,1838.58 R235.1@1721.46,1844.62 ; R234.2@1721.46,1877.95 R235.1@1721.46,1844.62 ; U64.155@1933.07,1720.47 1933.07,1721.13 1899.78,1721.13 1776.29,1844.62 R235.1@1721.46,1844.62
GPADC5: R278.2 R279.1 U64.156 | length 297.4
  Top w6: R279.1@1721.46,1759.84 R278.2@1721.46,1793.19 ; R278.2@1721.46,1799.21 R278.2@1721.46,1793.19 ; U64.156@1933.07,1681.1 1885.81,1681.1 1773.72,1793.19 R278.2@1721.46,1793.19
GPADC6: R280.2 R281.1 U64.157 | length 283.6
  Top w6: R281.1@1721.46,1681.1 R280.2@1721.46,1720.47 1777.72,1720.47 1856.46,1641.73 U64.157@1933.07,1641.73
HBIAS: C226.2 R282.2 UA1.2 | length 1699.2
  Top w6: R282.2@1094.49,3256.89 1114.34,3237.04 1114.34,3226.61 1119.38,3221.57 1137.8,3221.57 C226.2@1137.8,3223.43 1209,3223.43 1321.59,3110.84 1321.59,3101.09 v1(1317.49,3101.09) ; UA1.2@2377.16,3245.1 2377.16,3263.67 2385.91,3272.42 2385.91,3323.06 v1(2379.17,3323.34)
  Bottom w6: v1(1317.49,3101.09) 1325.44,3109.04 1388.22,3109.04 1469.28,3027.98 2133.85,3027.98 2240.95,3135.09 2240.95,3252.39 2325.32,3336.76 2365.75,3336.76 v1(2379.17,3323.34)
HCEC: Q1.2 R27.1 U64.39 | length 1556.5
  Top w6: U64.39@3507.87,460.63 3513.91,460.63 3825.67,772.39 4631.92,772.39 4659.21,745.1 4659.21,697.28 4695.64,660.85 4727.61,660.85 4733.36,655.1 4733.36,637.8 R27.1@4733.27,637.8 4778.44,592.62 Q1.2@4822.46,592.62
HDMI-5V: D85.2 D87.1 R30.2 R31.2 U17.18 | length 1215.2
  Top w10: D87.1@4734.54,716.54 4734.54,716.38 v1(4763.3,716.38) 4786.42,716.38 R31.2@4786.42,716.54 ; v1(4762.49,774.82) 4786.42,774.82 R30.2@4786.42,771.65
  Top w12: U17.18@5062.99,712.6 5143.03,712.6
  Top w30: v1(4500.12,705.49) 4527.36,705.49 4535.43,697.41 D85.2@4535.43,702.86 ; 5143.03,712.6 v1(5186.16,712.6)
  Bottom w10: 4737.65,838.2 4737.65,834.18 ; v1(4763.3,716.38) 4762.49,717.19 v1(4762.49,774.82) 4762.27,774.6 4737.65,799.21 4737.65,820.84 ; 4737.65,820.84 4746.29,829.48 4741.59,834.18 4737.65,834.18 ; 4737.65,820.84 4737.65,834.07 ; 4737.65,820.84 4730.43,828.06 4731.64,828.06 4737.65,834.07 ; 4737.65,834.07 4737.65,834.18
  Bottom w30: v1(4500.12,705.49) 4632.83,838.2 4737.65,838.2 4955.85,838.2 5081.45,712.6 v1(5186.16,712.6)
HDMI-HCEC: Q1.3 R28.2 U17.13 U18.1 U18.10 | length 605.7
  Top w6: Q1.3@4742.46,555.12 4742.46,554.63 4773.86,554.47 v1(4844.31,554.47) ; R28.2@4819.88,811.02 4824.71,806.2 v1(4844.96,806.2) 4844.96,803.15 U18.1@4872.72,803.15 4922.2,803.15 4930.07,811.02 U17.13@5062.99,811.02
  Bottom w6: v1(4844.31,554.47) 4844.31,805.55 v1(4844.96,806.2)
HHPD: R29.1 R32.1 U64.40 | length 1524.3
  Top w6: U64.40@3507.87,500 3535.21,500 3819.71,784.5 4636.82,784.5 4671.21,750.11 4671.21,702.63 4700.99,672.85 4751.36,672.85 R32.1@4786.42,637.8 R29.1@4786.42,677.17
HHPD1: R29.2 U17.19 U18.5 U18.6 | length 284.7
  Top w6: R29.2@4819.88,677.17 4844.68,701.96 4844.68,717.27 4851.82,724.41 U18.5@4872.72,724.41 4975.68,724.41 5007.17,692.91 U17.19@5062.99,692.91
HP-DET: R23.1 RA12.2 RA14.2 RA22.1 | length 1774
  Top w6: R23.1@1267.72,3306.1 1267.72,3211.55 1439.18,3040.09 1554.47,3040.09 1686.49,2908.07 1969.64,2908.07 v1(1979.09,2917.52) ; RA14.2@2544.29,2960.63 2544.29,2960.72 v1(2569.11,2960.72) 2593.5,2960.72 RA22.1@2593.5,2960.63 ; RA12.2@2544.29,3118.11 2562.42,3118.11 2571.88,3108.65 2571.88,3023.67 v1(2568.41,3020.2)
  Bottom w6: v1(1979.09,2917.52) 1996.57,2935.01 2157.97,2935.01 2175.05,2952.09 2560.48,2952.09 v1(2569.11,2960.72) 2569.11,3019.5 v1(2568.41,3020.2)
HP-DET-PE11: RA22.2 U64.129 | length 911.9
  Top w6: U64.129@2090.55,2704.73 2090.55,2678.66 2099.11,2670.1 2185.45,2670.1 2186.5,2672.02 v1(2188.97,2670.67) ; RA22.2@2626.97,2960.63 2650.18,2937.42 v1(2650.18,2916.02)
  Bottom w6: v1(2188.97,2670.67) 2189.47,2674.12 2189.47,2742.01 2170.1,2761.38 2170.1,2895.49 2198.69,2924.08 2642.12,2924.08 v1(2650.18,2916.02)
HPOUTFB-1: D16.2 J36.2 RA2.2 RN1.2 | length 318.1
  Top w6: RA2.2@964.57,3339.57 965.83,3340.83 D16.2@1051.18,3340.83 1051.18,3547.95 1062.99,3559.76 J36.2@1062.99,3566.93
HPOUTFB-2: C183.1 CA91.2 R26.1 R196.2 RA2.1 RN2.1 UA1.18 | length 1602.6
  Top w6: RN2.1@881.89,3306.1 881.89,3268.1 893.1,3256.89 R26.1@921.26,3256.89 C183.1@964.57,3256.89 ; RA2.1@964.57,3306.1 C183.1@964.57,3256.89 ; R196.2@1007.87,3174.21 v1(1007.88,3198.14) CA91.2@1007.87,3223.43 991.14,3240.16 981.3,3240.16 C183.1@964.57,3256.89 ; v1(1073.77,3198) 1217.45,3198 1288.57,3126.89 1288.57,3121.14 v1(1282.59,3121.14) ; v1(2179.71,3102.16) 2182.88,3105.34 UA1.18@2221.65,3105.34
  Bottom w6: v1(1007.88,3198.14) 1073.63,3198.14 v1(1073.77,3198) ; v1(1282.59,3121.14) 1393.17,3121.14 1474.33,3039.98 2117.53,3039.98 v1(2179.71,3102.16)
HPOUTL-2: C88.2 UA1.17 | length 994.9
  Top w6: C88.2@1311.02,3227.36 1326.91,3227.36 1333.6,3220.67 1333.6,3185.39 1364.55,3154.44 1595.6,3154.44 v1(1603.25,3146.79) ; v1(2178.64,3130.82) 2188.37,3121.09 UA1.17@2221.65,3121.09
  Bottom w6: v1(1603.25,3146.79) 1611.27,3154.81 1671.07,3154.81 1710.68,3115.2 2163.01,3115.2 v1(2178.64,3130.82)
HPOUTR-2: C89.2 UA1.19 | length 1014.6
  Top w6: C89.2@1366.14,3227.36 1350.14,3227.36 1345.6,3222.82 1345.6,3190.67 1369.82,3166.45 1594.5,3166.45 v1(1603.72,3175.67) ; v1(2150.86,3135.2) 2150.86,3098.3 2167.07,3082.1 2187.94,3082.1 2195.44,3089.59 UA1.19@2221.65,3089.59
  Bottom w6: v1(1603.72,3175.67) 1612.57,3166.82 1676.13,3166.82 1715.75,3127.2 2142.86,3127.2 v1(2150.86,3135.2)
HS-MIC-1: D15.2 J36.5 RA1.2 RN2.2 | length 1080.9
  Top w6: RN2.2@881.89,3339.57 RA1.2@921.26,3339.57 921.26,3395.68 v1(920.51,3396.43) ; J36.5@1338.58,3775.2 1358.27,3775.2 1421.26,3712.2 1421.26,3409.54 v1(1422.05,3394.57) 1421.26,3394.57 D15.2@1421.26,3340.83
  Bottom w6: v1(920.51,3396.43) 920.96,3396.43 920.96,3394.57 v1(1422.05,3394.57)
HS-MIC-2: C184.1 CA91.1 R195.2 R282.1 RA1.1 RN1.1 | length 311.4
  Top w6: RA1.1@921.26,3306.1 935.35,3306.1 939.86,3301.59 v1(939.86,3281.94) ; RN1.1@1007.87,3306.1 v1(1007.88,3282.43) CA91.1@1007.87,3256.89 1026.72,3238.04 1026.72,3231.44 1034.73,3223.43 C184.1@1051.18,3223.43 ; R195.2@1051.18,3174.21 C184.1@1051.18,3223.43 ; R282.1@1094.49,3223.43 C184.1@1051.18,3223.43
  Bottom w6: v1(939.86,3281.94) 1007.88,3281.94 v1(1007.88,3282.43)
HSCL: R30.1 U17.15 U18.2 U18.9 U64.42 | length 1708.9
  Top w6: U64.42@3507.87,578.74 3521.01,565.6 3543.38,565.6 3793.93,816.15 4671.51,816.15 4734.85,752.81 4801.04,752.81 R30.1@4819.88,771.65 4831.69,783.46 U18.2@4872.72,783.46 4915.8,783.46 4916.89,784.39 4984.3,784.39 4997.04,771.65 U17.15@5062.99,771.65
HSDA: R31.1 U17.16 U18.4 U18.7 U64.41 | length 1715.7
  Top w6: U64.41@3507.87,539.37 3522.07,553.57 3548.41,553.57 3798.87,804.03 4666.54,804.03 4729.76,740.81 4795.61,740.81 R31.1@4819.88,716.54 4847.44,744.09 U18.4@4872.72,744.09 4986.8,744.09 4994.68,751.97 U17.16@5062.99,751.97
HTX0N: U16.2 U16.9 U17.9 U64.45 | length 1654.9
  Top w6: U64.45@3507.87,696.85 3517.72,696.85 3531.9,711.04 3557.9,711.04 3752.78,905.91 4857.07,905.91 4861.42,901.57 U16.2@4872.72,901.57 4916.62,901.57 4920.92,905.87 4997.14,905.87 5015.28,887.73 5062.99,887.73 U17.9@5062.99,889.76
HTX0P: U16.1 U16.10 U17.7 U64.46 | length 1653.3
  Top w6: U64.46@3507.87,736.22 3517.72,736.22 3531.9,722.04 3553.21,722.04 3748.09,916.91 4857.71,916.91 4862.06,921.26 U16.1@4872.72,921.26 4917.6,921.26 4921.95,916.91 5001.01,916.91 5015.27,931.17 5062.99,931.17 U17.7@5062.99,929.13
HTX1N: DE1.5 DE1.6 U17.6 U64.47 | length 1643
  Top w6: U64.47@3507.87,775.59 3517.72,775.59 3531.9,789.78 3564.01,789.78 3739.2,964.97 4857.04,964.97 4861.38,960.63 DE1.5@4872.72,960.63 4917.72,960.63 4921.08,963.99 4998.08,963.99 5013.25,948.82 U17.6@5062.99,948.82
HTX1P: DE1.4 DE1.7 U17.4 U64.48 | length 1643
  Top w6: U64.48@3507.87,814.96 3517.72,814.96 3531.9,800.78 3559.44,800.78 3734.63,975.97 4857.47,975.97 4861.81,980.31 DE1.4@4872.72,980.31 4917.17,980.31 4922.49,974.99 4999.92,974.99 5013.12,988.19 U17.4@5062.99,988.19
HTX2N: DE1.2 DE1.9 U17.3 U64.49 | length 1638.3
  Top w6: U64.49@3507.87,854.33 3517.72,854.33 3531.9,868.52 3572.86,868.52 3728.36,1024.03 4857.31,1024.03 4861.66,1019.68 DE1.2@4872.72,1019.68 4917.51,1019.68 4921.54,1023.71 4997.41,1023.71 5015.29,1005.84 5062.99,1005.84 U17.3@5062.99,1007.87
HTX2P: DE1.1 DE1.10 U17.1 U64.50 | length 1637.2
  Top w6: U64.50@3507.87,893.7 3517.72,893.7 3531.9,879.52 3568.22,879.52 3723.72,1035.02 4857.85,1035.02 4862.2,1039.37 DE1.1@4872.72,1039.37 4917.61,1039.37 4922.27,1034.71 5000.71,1034.71 5015.28,1049.28 5062.99,1049.28 U17.1@5062.99,1047.24
HTXCN: U16.5 U16.6 U17.12 U64.43 | length 1660.2
  Top w6: U64.43@3507.87,618.11 3517.72,618.11 3531.9,632.3 3557.39,632.3 3771.95,846.86 4858.02,846.86 4862.36,842.52 U16.5@4872.72,842.52 4917.58,842.52 4921.92,846.86 4997.04,846.86 5013.19,830.71 U17.12@5062.99,830.71
HTXCP: U16.4 U16.7 U17.10 U64.44 | length 1658.5
  Top w6: U64.44@3507.87,657.48 3517.72,657.48 3531.9,643.3 3552.48,643.3 3767.04,857.86 4857.85,857.86 4862.19,862.2 U16.4@4872.72,862.2 4918.03,862.2 4922.37,857.86 5000.84,857.86 5013.06,870.08 U17.10@5062.99,870.08
HUB1-DM3: U10.15 U11.2 | length 91.4
  Top w6: U10.15@653.54,1914.37 669.29,1914.37 674.22,1919.3 719.43,1919.3 721.41,1917.32 U11.2@742.13,1917.32
HUB1-DP3: U10.16 U11.1 | length 93.4
  Top w6: U10.16@653.54,1935.24 669.29,1935.24 674.21,1930.31 716.29,1930.31 722.98,1937.01 U11.1@742.13,1937.01
I2S0-BCLK: U64.111 UA1.29 | length 686.7
  Top w6: UA1.29@2377.16,3044.32 2377.16,2891.7 2460.67,2808.19 2754.8,2808.19 2799.21,2763.78 U64.111@2799.21,2704.73
I2S0-DIN0: U64.114 UA1.27 | length 606.3
  Top w6: UA1.27@2345.66,3044.32 2345.66,2888.91 2450.42,2784.15 2668.48,2784.15 2681.1,2771.53 U64.114@2681.1,2704.73
I2S0-DOUT0: U64.113 UA1.26 | length 658
  Top w6: UA1.26@2329.92,3044.32 2329.92,2887.45 2445.22,2772.14 2652.17,2772.14 v1(2660.23,2764.08) ; v1(2719.65,2763.19) 2720.47,2762.37 U64.113@2720.47,2704.73
  Bottom w6: v1(2660.23,2764.08) 2720.13,2764.08 v1(2719.65,2763.19)
I2S0-LRCK: U64.112 UA1.28 | length 674.1
  Top w6: UA1.28@2361.41,3044.32 2361.41,2890.24 2455.49,2796.16 2744.79,2796.16 2759.84,2781.11 U64.112@2759.84,2704.73
I2S0-MCLK: U64.110 UA1.30 | length 703.4
  Top w6: UA1.30@2392.91,3044.32 2392.91,2893.15 2465.8,2820.26 2771.65,2820.26 2838.58,2753.33 U64.110@2838.58,2704.73
INTB: RE20.2 U15.31 | length 116
  Top w6: U15.31@4226.38,2618.11 4246.66,2618.11 4305.71,2559.06 RE20.2@4317.91,2559.06
IO-RESET: D130.1 K4.1 R298.2 U64.6 | length 3875.8
  Top w6: U64.6@2208.66,342.52 2208.66,350.39 2234.08,375.82 3447.34,375.82 3641.9,181.26 3712.14,111.05 3712.14,110.99 3774.49,48.64 3774.49,-157.48 3846.3,-229.29 4364.43,-229.29 4397.87,-195.85 4974.81,-195.85 4989.41,-181.25 4989.41,96.69 R298.2@5188.98,296.26 D130.1@5188.98,340.27 5188.98,342.27 5201.54,354.83 5252.47,354.83 K4.1@5259.84,362.2
IOVDD-CSI: CON1.39 CP8.1 D178.2 U64.37 | length 875.4
  Top w12: CON1.39@3163.51,-161.38 3163.51,-179.1 3176.65,-192.24 3190.02,-192.24
  Top w20: 3190.02,-192.24 3345.94,-192.24 3492.36,-45.82 3492.36,128.32 3476.69,143.98 D178.2@3456.69,143.98 CP8.1@3456.69,199.8 3476.54,199.8 3486.7,209.97 3486.7,264.74 3429.13,322.31 U64.37@3429.13,342.52
LCD0-EN: D41.1 J3.40 R209.2 U64.81 | length 2664.5
  Top w6: U64.81@3507.87,2114.17 3536.74,2114.17 3724.33,2301.76 4160.35,2301.76 4228.83,2370.24 4379.61,2370.24 4413.62,2404.26 4537.92,2404.26 4597.35,2463.69 4597.35,2595.12 4613.02,2610.79 4613.02,2711.44 J3.40@4677.17,2775.59 4677.17,2790.64 D41.1@4558.35,2909.45 ; v1(4708.9,2830.58) 4704.16,2835.32 4704.16,3483.69 R209.2@4830.71,3610.24
  Bottom w6: J3.40@4677.17,2775.59 4708.9,2807.33 v1(4708.9,2830.58)
LCD0-HSYNC: D44.1 J3.29 U64.78 | length 1424.5
  Top w6: U64.78@3507.87,1996.06 3552.85,1996.06 3786.71,2229.92 4188.58,2229.92 4255.12,2296.45 4444.9,2296.45 4467.66,2319.22 4507.52,2319.22 4527.63,2299.12 D44.1@4528.9,2299.12 4530.9,2299.12 4573.95,2342.17 4716.19,2342.17 J3.29@4755.91,2381.89
LCD0-PWM: D42.1 J3.39 R215.1 U13.4 U64.80 | length 3248.2
  Top w6: U64.80@3507.87,2074.8 3540.45,2074.8 3755.41,2289.76 4165.33,2289.76 4233.73,2358.16 4384.85,2358.16 4418.89,2392.2 4542.83,2392.2 4625.42,2474.79 4625.42,2573.59 v1(4617.37,2583.79) 4625.22,2591.64 4625.22,2700.06 4661.38,2736.22 4716.53,2736.22 J3.39@4755.91,2775.59 4735.52,2775.59 D42.1@4558.35,2952.76 ; U13.4@4299.21,1454.72 4298.95,1454.72 v1(4298.95,1477.56) R215.1@4298.95,1499.28 ; R215.1@4299.21,1499.02 R215.1@4298.95,1499.28 ; R215.1@4298.95,1499.28 R215.1@4298.23,1500 4298.95,1500 R215.1@4298.95,1499.28
  Bottom w6: v1(4298.95,1477.56) 4280.91,1495.61 4280.91,1664.52 4553.84,1937.45 4553.84,2520.26 v1(4617.37,2583.79)
LCD0-VSYNC: D43.1 J3.30 U64.79 | length 1313.7
  Top w6: U64.79@3507.87,2035.43 3575.13,2035.43 3781.64,2241.94 4183.39,2241.94 4250.26,2308.81 4440.28,2308.81 4462.69,2331.22 4501.49,2331.22 4511.32,2341.05 4511.32,2341.78 4523.87,2354.33 D43.1@4525.87,2354.33 ; D43.1@4525.87,2353.83 D43.1@4525.87,2354.33 ; J3.30@4677.17,2381.89 4649.61,2354.33 D43.1@4525.87,2354.33
LCD-PE3: J40.1 R295.2 U64.7 | length 965.9
  Top w6: J40.1@1541.73,150 1539.94,152.17 1537.49,154.62 R295.2@1537.49,294.84 1568.34,294.84 1584.48,310.98 1584.48,352.7 1602.92,371.14 1841.55,371.14 1914.07,298.62 2212,298.62 2248.03,334.65 U64.7@2248.03,342.52
LCD-PE4: J40.2 R296.2 U64.8 | length 897.5
  Top w6: J40.2@1641.73,150 1641.73,297.62 1643.85,299.74 R296.2@1643.85,294.91 ; R296.2@1643.79,294.84 R296.2@1643.85,294.91 ; U64.8@2287.4,342.52 2287.4,334.65 2239.37,286.62 1909.1,286.62 1836.58,359.14 1684.2,359.14 1675.28,350.23 1675.28,326.34 R296.2@1643.85,294.91
LCD-PE5: J40.3 R297.2 U64.9 | length 828
  Top w6: J40.3@1741.73,150 1741.73,294.36 R297.2@1742.21,294.84 1763.87,316.5 1763.87,340.31 1770.7,347.14 1831.61,347.14 1904.13,274.62 2266.74,274.62 2326.77,334.65 U64.9@2326.77,342.52
LCD_LR: J39.33 R201.2 R203.1 | length 137.1
  Top w6: R201.2@5143.7,1972.44 R203.1@5143.7,1933.07 5166.08,1933.07 5197.57,1964.57 J39.33@5228.35,1964.57
LCD_RST-PL7: C235.2 D45.1 J39.5 R290.2 U64.177 | length 5665.8
  Top w6: U64.177@1933.07,854.33 1989.34,854.33 2339.67,504 3321.72,504 3353.21,535.49 3353.21,2049.8 v1(3340.1,2062.91) ; v1(3566.66,2064.01) 3765.83,2263.21 4176.28,2263.21 4244.49,2331.41 4392.23,2331.41 4441.01,2380.2 4547.8,2380.2 4637.42,2469.82 4637.42,2633.6 4660.95,2657.12 4945.58,2657.12 4961.16,2641.54 5049.42,2641.54 5072.4,2664.52 5120.91,2664.52 R290.2@5139.76,2645.67 R290.2@5139.76,2646.2 ; D45.1@5141.03,2732.28 5141.03,2689.53 5140.12,2688.62 5139.76,2688.26 R290.2@5139.76,2646.2 ; v1(5167.61,2595.26) 5167.61,2634.69 5156.1,2646.2 R290.2@5139.76,2646.2 ; J39.5@5228.35,2515.75 5274.23,2515.75 v1(5295.61,2537.13)
  Bottom w6: v1(3340.1,2062.91) 3340.1,2064.57 3566.66,2064.57 v1(3566.66,2064.01) ; v1(5167.61,2595.26) 5168.65,2595.26 5185.38,2578.53 5239.32,2578.53 5280.72,2537.13 v1(5295.61,2537.13)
